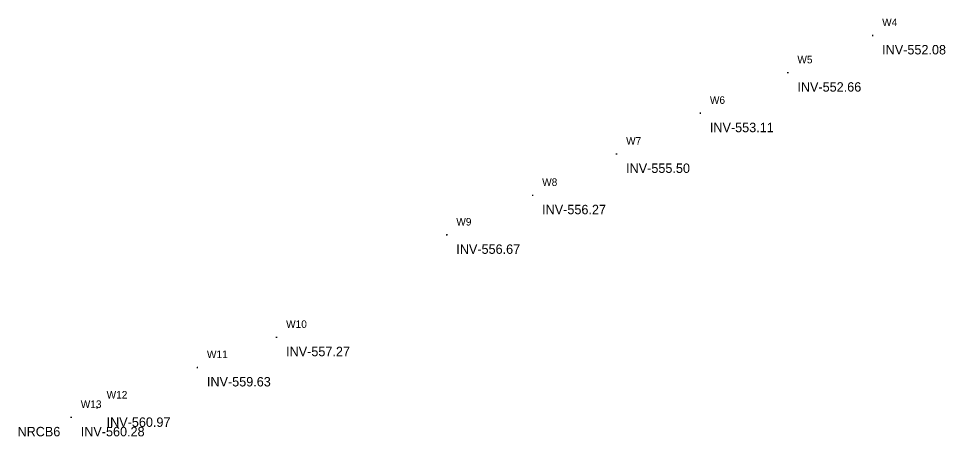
# Model space of a CAD drawing. Extents: x 1742532 to 1750760, y 651493 to 652721.
# Drawn here: x 1745895.4 to 1746386.3, y 651842.2 to 652063.5 of the extents above; entities that cross this region are included whole.
import ezdxf

# ---------------------------------------------------------------- set-up
doc = ezdxf.new("R2010")
doc.units = 0
for name, color, linetype in [('SURVEY - DRAINAGE - Storm Sewer - Points - Elevations', 7, 'Continuous'), ('SURVEY - DRAINAGE - Storm Sewer - Points - Locators', 7, 'Continuous'), ('SURVEY - DRAINAGE - Storm Sewer - Points - Numbers', 7, 'Continuous'), ('SURVEY - DRAINAGE - Storm Sewer Text', 7, 'Continuous')]:
    doc.layers.add(name, color=color, linetype=linetype)

msp = doc.modelspace()

# ---------------------------------------------------------------- linework, layer by layer
at = {"layer": 'SURVEY - DRAINAGE - Storm Sewer - Points - Locators'}
for p, q in [((1746348.04, 652054.48), (1746347.54, 652054.48)), ((1746347.79, 652054.23), (1746347.79, 652054.73)), ((1746347.79, 652054.48), (1746347.79, 652054.48)), ((1746347.79, 652054.48), (1746347.79, 652054.48)), ((1746303.14, 652034.77), (1746302.64, 652034.77)), ((1746302.89, 652034.52), (1746302.89, 652035.02)), ((1746302.89, 652034.77), (1746302.89, 652034.77)), ((1746302.89, 652034.77), (1746302.89, 652034.77)), ((1746256.81, 652013.31), (1746256.31, 652013.31)), ((1746256.56, 652013.06), (1746256.56, 652013.56)), ((1746256.56, 652013.31), (1746256.56, 652013.31)), ((1746256.56, 652013.31), (1746256.56, 652013.31)), ((1746212.43, 651991.74), (1746211.93, 651991.74)), ((1746212.18, 651991.49), (1746212.18, 651991.99)), ((1746212.18, 651991.74), (1746212.18, 651991.74)), ((1746212.18, 651991.74), (1746212.18, 651991.74)), ((1746167.96, 651969.86), (1746167.46, 651969.86)), ((1746167.71, 651969.61), (1746167.71, 651970.11)), ((1746167.71, 651969.86), (1746167.71, 651969.86)), ((1746167.71, 651969.86), (1746167.71, 651969.86)), ((1746122.5, 651948.9), (1746122, 651948.9)), ((1746122.25, 651948.65), (1746122.25, 651949.15)), ((1746122.25, 651948.9), (1746122.25, 651948.9)), ((1746122.25, 651948.9), (1746122.25, 651948.9)), ((1746032.35, 651894.69), (1746031.85, 651894.69)), ((1746032.1, 651894.44), (1746032.1, 651894.94)), ((1746032.1, 651894.69), (1746032.1, 651894.69)), ((1746032.1, 651894.69), (1746032.1, 651894.69)), ((1745990.42, 651878.7), (1745989.92, 651878.7)), ((1745990.17, 651878.45), (1745990.17, 651878.95)), ((1745990.17, 651878.7), (1745990.17, 651878.7)), ((1745990.17, 651878.7), (1745990.17, 651878.7)), ((1745937.29, 651857.29), (1745936.79, 651857.29)), ((1745937.04, 651857.04), (1745937.04, 651857.54)), ((1745937.04, 651857.29), (1745937.04, 651857.29)), ((1745937.04, 651857.29), (1745937.04, 651857.29)), ((1745923.59, 651852.29), (1745923.09, 651852.29)), ((1745923.34, 651852.04), (1745923.34, 651852.54)), ((1745923.34, 651852.29), (1745923.34, 651852.29)), ((1745923.34, 651852.29), (1745923.34, 651852.29))]:
    msp.add_line(p, q, dxfattribs=at)

# ---------------------------------------------------------------- texts
at = {"layer": 'SURVEY - DRAINAGE - Storm Sewer - Points - Elevations'}
for s, p in [('INV-552.08', (1746352.79, 652044.48)), ('INV-552.66', (1746307.89, 652024.77)), ('INV-553.11', (1746261.56, 652003.31)), ('INV-555.50', (1746217.18, 651981.74)), ('INV-556.27', (1746172.71, 651959.86)), ('INV-556.67', (1746127.25, 651938.9)), ('INV-557.27', (1746037.1, 651884.69)), ('INV-559.63', (1745995.17, 651868.7)), ('INV-560.97', (1745942.04, 651847.29)), ('INV-560.28', (1745928.34, 651842.29))]:
    msp.add_text(s, height=5, dxfattribs=at).set_placement(p)
at = {"layer": 'SURVEY - DRAINAGE - Storm Sewer - Points - Numbers'}
for s, p in [('W4', (1746352.79, 652059.48)), ('W5', (1746307.89, 652039.77)), ('W6', (1746261.56, 652018.31)), ('W7', (1746217.18, 651996.74)), ('W8', (1746172.71, 651974.86)), ('W9', (1746127.25, 651953.9)), ('W10', (1746037.1, 651899.69)), ('W11', (1745995.17, 651883.7)), ('W12', (1745942.04, 651862.29)), ('W13', (1745928.34, 651857.29))]:
    msp.add_text(s, height=4, dxfattribs=at).set_placement(p)
at = {"layer": 'SURVEY - DRAINAGE - Storm Sewer Text'}
msp.add_text('NRCB6', height=5, dxfattribs=at).set_placement((1745894.85, 651842.29))

doc.saveas('drawing.dxf')
